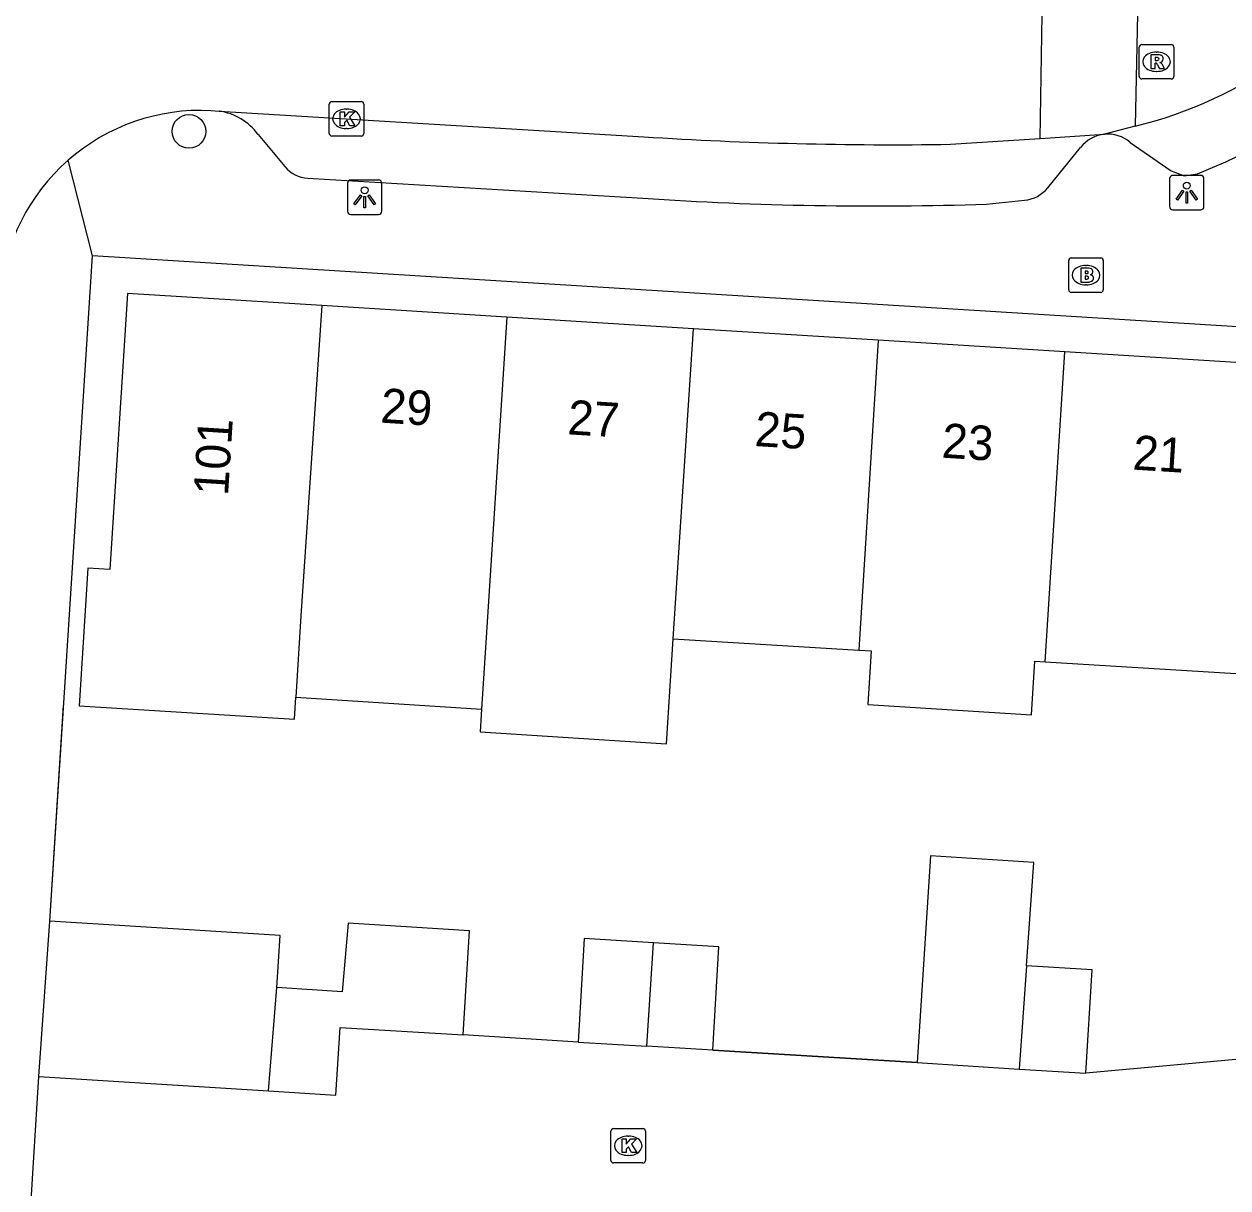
# Model space of a CAD drawing. Extents: x 160107 to 160928, y 382056 to 382918.
# Drawn here: x 160567.1 to 160601.98, y 382582.87 to 382616.6 of the extents above; entities that cross this region are included whole.
import ezdxf

# ---------------------------------------------------------------- set-up
doc = ezdxf.new("R2010")
doc.units = 0
for name, color, linetype in [('IMGEO_Boom', 7, 'Continuous'), ('IMGEO_Brandkraan', 7, 'Continuous'), ('IMGEO_Kolk', 7, 'Continuous'), ('IMGEO_Lichtpunt', 7, 'Continuous'), ('IMGEO_Muur', 7, 'Continuous'), ('IMGEO_Pand', 7, 'Continuous'), ('IMGEO_Pand_nummerreeks', 7, 'Continuous'), ('IMGEO_Rijbaan_lokaal_open', 7, 'Continuous'), ('IMGEO_Rioolput', 7, 'Continuous'), ('IMGEO_Voetpad_open', 7, 'Continuous')]:
    doc.layers.add(name, color=color, linetype=linetype)

msp = doc.modelspace()

# ---------------------------------------------------------------- linework, layer by layer
at = {"layer": 'IMGEO_Boom'}
msp.add_circle((160571.877, 382613.488), 0.489, dxfattribs=at)
at = {"layer": 'IMGEO_Brandkraan'}
for p, q in [((160597.368, 382608.896), (160597.368, 382609.748)), ((160597.443, 382609.822), (160598.295, 382609.822)), ((160597.856, 382609.602), (160597.881, 382609.602)), ((160598.369, 382609.748), (160598.369, 382608.896)), ((160598.295, 382608.822), (160597.443, 382608.822)), ((160597.879, 382609.042), (160597.854, 382609.042))]:
    msp.add_line(p, q, dxfattribs=at)
for points in [[(160597.368, 382608.896), (160597.368, 382609.748)], [(160597.443, 382609.822), (160598.295, 382609.822)], [(160597.716, 382609.522), (160597.716, 382609.122), (160597.929, 382609.122)], [(160597.947, 382609.522), (160597.716, 382609.522)], [(160598.369, 382609.748), (160598.369, 382608.896)], [(160597.895, 382609.441), (160597.841, 382609.441), (160597.841, 382609.365)], [(160597.841, 382609.365), (160597.894, 382609.365)], [(160597.903, 382609.289), (160597.841, 382609.289), (160597.841, 382609.208)], [(160597.841, 382609.208), (160597.903, 382609.208)], [(160598.295, 382608.822), (160597.443, 382608.822)]]:
    msp.add_lwpolyline(points, dxfattribs=at)
for centre, radius, start, end in [((160597.445, 382609.746), 0.0765, 91.552, 178.448), ((160597.445, 382609.746), 0.0765, 91.552, 178.448), ((160597.951, 382609.377), 0.145, 59.4692, 91.5367), ((160597.976, 382609.424), 0.0922, 285.5137, 58.1501), ((160598.293, 382609.746), 0.0765, 1.552, 88.448), ((160598.293, 382609.746), 0.0765, 1.552, 88.448), ((160597.896, 382609.403), 0.0379, 267.8285, 90.9355), ((160597.904, 382609.248), 0.0404, 269.8759, 90.5077), ((160597.935, 382609.373), 0.251, 268.6676, 293.5347), ((160597.981, 382609.232), 0.105, 301.3115, 78.989), ((160597.445, 382608.898), 0.0765, 181.552, 268.448), ((160597.445, 382608.898), 0.0765, 181.552, 268.448), ((160598.293, 382608.898), 0.0765, 271.552, 358.448), ((160598.293, 382608.898), 0.0765, 271.552, 358.448)]:
    msp.add_arc(centre, radius, start, end, dxfattribs=at)
for centre, major_axis, ratio, start_param, end_param in [((160597.855, 382609.322), (-0.387, 0.002), 0.722429, 4.712389, 7.853982), ((160597.88, 382609.322), (-0.39, 0.002), 0.717154, 1.570796, 4.712389)]:
    msp.add_ellipse(centre, major_axis=major_axis, ratio=ratio, start_param=start_param, end_param=end_param, dxfattribs=at)
at = {"layer": 'IMGEO_Kolk'}
for p, q in [((160575.941, 382613.426), (160575.941, 382614.278)), ((160576.016, 382614.352), (160576.868, 382614.352)), ((160576.429, 382614.132), (160576.454, 382614.132)), ((160576.942, 382614.278), (160576.942, 382613.426)), ((160576.868, 382613.352), (160576.016, 382613.352)), ((160576.452, 382613.572), (160576.427, 382613.572)), ((160584.105, 382583.668), (160584.105, 382584.52)), ((160584.18, 382584.594), (160585.032, 382584.594)), ((160584.593, 382584.374), (160584.618, 382584.374)), ((160585.106, 382584.52), (160585.106, 382583.668)), ((160584.616, 382583.814), (160584.591, 382583.814)), ((160585.032, 382583.594), (160584.18, 382583.594))]:
    msp.add_line(p, q, dxfattribs=at)
for points in [[(160575.941, 382613.426), (160575.941, 382614.278)], [(160576.016, 382614.352), (160576.868, 382614.352)], [(160576.262, 382614.052), (160576.385, 382614.052), (160576.385, 382613.901), (160576.515, 382614.052), (160576.679, 382614.052), (160576.533, 382613.901), (160576.686, 382613.652), (160576.534, 382613.652), (160576.449, 382613.816), (160576.385, 382613.749), (160576.385, 382613.652), (160576.262, 382613.652), (160576.262, 382614.052)], [(160576.942, 382614.278), (160576.942, 382613.426)], [(160576.868, 382613.352), (160576.016, 382613.352)], [(160584.105, 382583.668), (160584.105, 382584.52)], [(160584.18, 382584.594), (160585.032, 382584.594)], [(160585.106, 382584.52), (160585.106, 382583.668)], [(160584.426, 382584.294), (160584.549, 382584.294), (160584.549, 382584.143), (160584.679, 382584.294), (160584.843, 382584.294), (160584.697, 382584.143), (160584.85, 382583.894), (160584.698, 382583.894), (160584.613, 382584.058), (160584.549, 382583.991), (160584.549, 382583.894), (160584.426, 382583.894), (160584.426, 382584.294)], [(160585.032, 382583.594), (160584.18, 382583.594)]]:
    msp.add_lwpolyline(points, dxfattribs=at)
for centre, start, end in [((160576.018, 382614.276), 91.552, 178.448), ((160576.018, 382614.276), 91.552, 178.448), ((160576.866, 382614.276), 1.552, 88.448), ((160576.866, 382614.276), 1.552, 88.448), ((160576.018, 382613.428), 181.552, 268.448), ((160576.018, 382613.428), 181.552, 268.448), ((160576.866, 382613.428), 271.552, 358.448), ((160576.866, 382613.428), 271.552, 358.448), ((160584.182, 382584.518), 91.552, 178.448), ((160584.182, 382584.518), 91.552, 178.448), ((160585.03, 382584.518), 1.552, 88.448), ((160585.03, 382584.518), 1.552, 88.448), ((160584.182, 382583.67), 181.552, 268.448), ((160584.182, 382583.67), 181.552, 268.448), ((160585.03, 382583.67), 271.552, 358.448), ((160585.03, 382583.67), 271.552, 358.448)]:
    msp.add_arc(centre, 0.0765, start, end, dxfattribs=at)
for centre, major_axis, ratio, start_param, end_param in [((160576.428, 382613.852), (-0.387, 0.002), 0.722429, 4.712389, 7.853982), ((160576.453, 382613.852), (-0.39, 0.002), 0.717154, 1.570796, 4.712389), ((160584.592, 382584.094), (-0.387, 0.002), 0.722429, 4.712389, 7.853982), ((160584.617, 382584.094), (-0.39, 0.002), 0.717154, 1.570796, 4.712389)]:
    msp.add_ellipse(centre, major_axis=major_axis, ratio=ratio, start_param=start_param, end_param=end_param, dxfattribs=at)
at = {"layer": 'IMGEO_Lichtpunt'}
for p, q in [((160576.47, 382611.983), (160576.47, 382611.176)), ((160576.47, 382611.983), (160576.47, 382611.176)), ((160577.372, 382612.078), (160576.564, 382612.078)), ((160577.372, 382612.078), (160576.564, 382612.078)), ((160577.466, 382611.176), (160577.466, 382611.983)), ((160577.466, 382611.176), (160577.466, 382611.983)), ((160600.291, 382612.118), (160600.291, 382611.311)), ((160600.291, 382612.118), (160600.291, 382611.311)), ((160601.193, 382612.213), (160600.385, 382612.213)), ((160601.193, 382612.213), (160600.385, 382612.213)), ((160601.287, 382611.311), (160601.287, 382612.118)), ((160601.287, 382611.311), (160601.287, 382612.118)), ((160576.564, 382611.082), (160577.372, 382611.082)), ((160576.564, 382611.082), (160577.372, 382611.082)), ((160600.385, 382611.217), (160601.193, 382611.217)), ((160600.385, 382611.217), (160601.193, 382611.217))]:
    msp.add_line(p, q, dxfattribs=at)
for points in [[(160576.844, 382611.647), (160576.883, 382611.619), (160576.695, 382611.357), (160576.657, 382611.384), (160576.844, 382611.647)], [(160576.946, 382611.599), (160576.993, 382611.599), (160576.993, 382611.277), (160576.946, 382611.277), (160576.946, 382611.599)], [(160577.056, 382611.619), (160577.094, 382611.646), (160577.281, 382611.384), (160577.242, 382611.356), (160577.056, 382611.619)], [(160600.665, 382611.782), (160600.704, 382611.754), (160600.516, 382611.492), (160600.478, 382611.519), (160600.665, 382611.782)], [(160600.767, 382611.734), (160600.814, 382611.734), (160600.814, 382611.412), (160600.767, 382611.412), (160600.767, 382611.734)], [(160600.877, 382611.754), (160600.915, 382611.781), (160601.102, 382611.519), (160601.063, 382611.491), (160600.877, 382611.754)]]:
    msp.add_lwpolyline(points, dxfattribs=at)
for centre in [(160600.79, 382611.916), (160576.969, 382611.781)]:
    msp.add_circle(centre, 0.0994, dxfattribs=at)
for centre, start, end in [((160576.564, 382611.983), 90, 180), ((160576.564, 382611.983), 90, 180), ((160577.372, 382611.983), 0, 90), ((160577.372, 382611.983), 0, 90), ((160600.385, 382612.118), 90, 180), ((160600.385, 382612.118), 90, 180), ((160601.193, 382612.118), 0, 90), ((160601.193, 382612.118), 0, 90), ((160600.385, 382611.311), 180, 270), ((160600.385, 382611.311), 180, 270), ((160601.193, 382611.311), 270, 0), ((160601.193, 382611.311), 270, 360), ((160576.564, 382611.176), 180, 270), ((160576.564, 382611.176), 180, 270), ((160577.372, 382611.176), 270, 0), ((160577.372, 382611.176), 270, 360)]:
    msp.add_arc(centre, 0.0946, start, end, dxfattribs=at)
at = {"layer": 'IMGEO_Muur'}
for points in [[(160567.843, 382590.6), (160568.24, 382596.851)], [(160587.052, 382586.864), (160592.981, 382586.504)]]:
    msp.add_lwpolyline(points, dxfattribs=at)
at = {"layer": 'IMGEO_Pand'}
for points in [[(160575.73, 382608.44), (160570.093, 382608.792), (160569.588, 382600.789), (160568.944, 382600.833), (160568.697, 382596.841), (160574.935, 382596.456), (160574.974, 382597.092)], [(160575.73, 382608.44), (160575.12, 382599.45), (160574.974, 382597.092)], [(160581.091, 382608.106), (160575.73, 382608.44)], [(160581.091, 382608.106), (160580.51, 382599.117), (160580.357, 382596.744)], [(160586.493, 382607.769), (160581.091, 382608.106)], [(160585.91, 382598.784), (160586.493, 382607.769)], [(160591.85, 382607.434), (160586.493, 382607.769)], [(160591.85, 382607.434), (160591.29, 382598.453)], [(160597.253, 382607.097), (160591.85, 382607.434)], [(160596.681, 382598.12), (160597.253, 382607.097)], [(160602.819, 382606.589), (160602.83, 382606.749), (160597.253, 382607.097)], [(160580.357, 382596.744), (160580.314, 382596.086), (160585.712, 382595.736), (160585.91, 382598.784)], [(160585.91, 382598.784), (160591.29, 382598.453)], [(160591.29, 382598.453), (160591.642, 382598.431), (160591.546, 382596.876), (160596.287, 382596.583), (160596.383, 382598.138), (160596.681, 382598.12)], [(160596.681, 382598.12), (160602.211, 382597.779), (160602.544, 382597.758), (160603.77, 382592.691), (160605.181, 382586.859)], [(160574.974, 382597.092), (160580.357, 382596.744)], [(160596.146, 382589.311), (160596.355, 382592.304), (160593.36, 382592.493), (160592.981, 382586.504)], [(160567.525, 382586.098), (160567.843, 382590.6)], [(160574.424, 382588.676), (160574.518, 382590.184), (160567.843, 382590.6)], [(160579.82, 382587.303), (160580.01, 382590.32), (160576.487, 382590.542), (160576.32, 382588.557), (160574.424, 382588.676)], [(160585.338, 382589.974), (160583.331, 382590.095), (160583.151, 382587.099)], [(160585.144, 382586.979), (160585.338, 382589.974)], [(160587.052, 382586.864), (160587.233, 382589.859), (160585.338, 382589.974)], [(160596.146, 382589.311), (160595.929, 382586.317)], [(160597.864, 382586.195), (160598.052, 382589.191), (160596.146, 382589.311)], [(160574.186, 382585.683), (160574.424, 382588.676)], [(160574.186, 382585.683), (160576.133, 382585.562), (160576.255, 382587.521), (160579.82, 382587.303)], [(160583.151, 382587.099), (160585.144, 382586.979)], [(160587.052, 382586.864), (160585.144, 382586.979)], [(160592.981, 382586.504), (160595.929, 382586.317)], [(160595.929, 382586.317), (160597.864, 382586.195)], [(160567.525, 382586.098), (160574.186, 382585.683)]]:
    msp.add_lwpolyline(points, dxfattribs=at)
at = {"layer": 'IMGEO_Rijbaan_lokaal_open'}
for points in [[(160599.429, 382620.147), (160599.295, 382613.642)], [(160596.539, 382613.283), (160596.638, 382619.282)], [(160572.51, 382614.088), (160572.749, 382614.074)], [(160572.749, 382614.074), (160585.053, 382613.331)], [(160596.539, 382613.283), (160598.409, 382613.405)], [(160599.295, 382613.642), (160598.409, 382613.405)], [(160593.941, 382613.114), (160596.539, 382613.283)], [(160583.151, 382587.099), (160579.82, 382587.303)], [(160592.981, 382586.504), (160587.052, 382586.864)], [(160605.181, 382586.859), (160597.864, 382586.195)], [(160569.255, 382582.058), (160567.288, 382582.195), (160567.525, 382586.098)]]:
    msp.add_lwpolyline(points, dxfattribs=at)
for centre, radius, start, end in [((160596.488, 382625.35), 12.04, 283.4844, 306.2862), ((160572.217, 382608.269), 5.826, 87.1182, 131.242), ((160592.22, 382724.76), 111.659, 266.31977, 270.88303), ((160572.216, 382608.27), 5.825, 131.2407, 175.3716)]:
    msp.add_arc(centre, radius, start, end, dxfattribs=at)
at = {"layer": 'IMGEO_Rioolput'}
for p, q in [((160599.412, 382615.08), (160599.412, 382615.932)), ((160599.487, 382616.006), (160600.339, 382616.006)), ((160599.9, 382615.786), (160599.925, 382615.786)), ((160600.413, 382615.932), (160600.413, 382615.08)), ((160599.923, 382615.226), (160599.898, 382615.226)), ((160600.339, 382615.006), (160599.487, 382615.006))]:
    msp.add_line(p, q, dxfattribs=at)
for points in [[(160599.412, 382615.08), (160599.412, 382615.932)], [(160599.487, 382616.006), (160600.339, 382616.006)], [(160600.413, 382615.932), (160600.413, 382615.08)], [(160600.001, 382615.704), (160599.749, 382615.706), (160599.749, 382615.306)], [(160599.749, 382615.306), (160599.873, 382615.306), (160599.873, 382615.468), (160599.884, 382615.468)], [(160599.927, 382615.625), (160599.873, 382615.625), (160599.873, 382615.544)], [(160599.873, 382615.544), (160599.925, 382615.544)], [(160599.931, 382615.439), (160600.002, 382615.306), (160600.142, 382615.306), (160600.077, 382615.432)], [(160600.339, 382615.006), (160599.487, 382615.006)]]:
    msp.add_lwpolyline(points, dxfattribs=at)
for centre, radius, start, end in [((160599.489, 382615.93), 0.0765, 91.552, 178.448), ((160599.489, 382615.93), 0.0765, 91.552, 178.448), ((160600.337, 382615.93), 0.0765, 1.552, 88.448), ((160600.337, 382615.93), 0.0765, 1.552, 88.448), ((160599.883, 382615.415), 0.0533, 26.0293, 88.6989), ((160599.909, 382615.733), 0.19, 274.7715, 282.9687), ((160599.933, 382615.529), 0.0964, 77.0061, 93.1865), ((160599.947, 382615.586), 0.0378, 276.6634, 79.6772), ((160600, 382615.594), 0.109, 350.3612, 89.416), ((160599.998, 382615.594), 0.112, 277.5842, 350.9817), ((160599.982, 382615.379), 0.108, 29.5134, 73.7905), ((160599.489, 382615.082), 0.0765, 181.552, 268.448), ((160599.489, 382615.082), 0.0765, 181.552, 268.448), ((160600.337, 382615.082), 0.0765, 271.552, 358.448), ((160600.337, 382615.082), 0.0765, 271.552, 358.448)]:
    msp.add_arc(centre, radius, start, end, dxfattribs=at)
for centre, major_axis, ratio, start_param, end_param in [((160599.899, 382615.506), (-0.387, 0.002), 0.722429, 4.712389, 7.853982), ((160599.924, 382615.506), (-0.39, 0.002), 0.717154, 1.570796, 4.712389)]:
    msp.add_ellipse(centre, major_axis=major_axis, ratio=ratio, start_param=start_param, end_param=end_param, dxfattribs=at)
at = {"layer": 'IMGEO_Voetpad_open'}
for points in [[(160646.97, 382651.686), (160602.42, 382607.815), (160569.084, 382609.884)], [(160573.881, 382613.401), (160574.655, 382612.469)], [(160596.762, 382611.853), (160597.711, 382613.019)], [(160599.152, 382613.169), (160600.338, 382612.341), (160600.71, 382612.202), (160601.102, 382612.26), (160601.924, 382612.606)], [(160569.084, 382609.884), (160568.376, 382612.65)], [(160575.321, 382612.131), (160585.028, 382611.551)], [(160594.987, 382611.381), (160596.087, 382611.49)], [(160567.843, 382590.6), (160569.084, 382609.884)]]:
    msp.add_lwpolyline(points, dxfattribs=at)
for centre, radius, start, end in [((160593.932, 382629.434), 18.629, 295.403, 310.6739), ((160572.511, 382612.386), 1.705, 36.5447, 81.9904), ((160598.502, 382612.412), 0.997, 95.3639, 142.5221), ((160598.505, 382612.418), 0.991, 49.2241, 95.5329), ((160575.378, 382613.069), 0.94, 219.6814, 266.5023), ((160595.989, 382612.48), 0.995, 275.6233, 320.9175), ((160591.699, 382710.58), 99.254, 266.14593, 271.89818)]:
    msp.add_arc(centre, radius, start, end, dxfattribs=at)

# ---------------------------------------------------------------- texts
at = {"layer": 'IMGEO_Pand_nummerreeks'}
for s, rotation, p in [('29', 356.4305, (160577.41, 382605.05)), ('27', 356.4305, (160582.83, 382604.711)), ('25', 356.4295, (160588.251, 382604.372)), ('101', 86.3848, (160573.008, 382602.916)), ('23', 356.4305, (160593.67, 382604.035)), ('21', 356.4295, (160599.204, 382603.689))]:
    msp.add_text(s, height=1, rotation=rotation, dxfattribs=at).set_placement(p)

doc.saveas('drawing.dxf')
